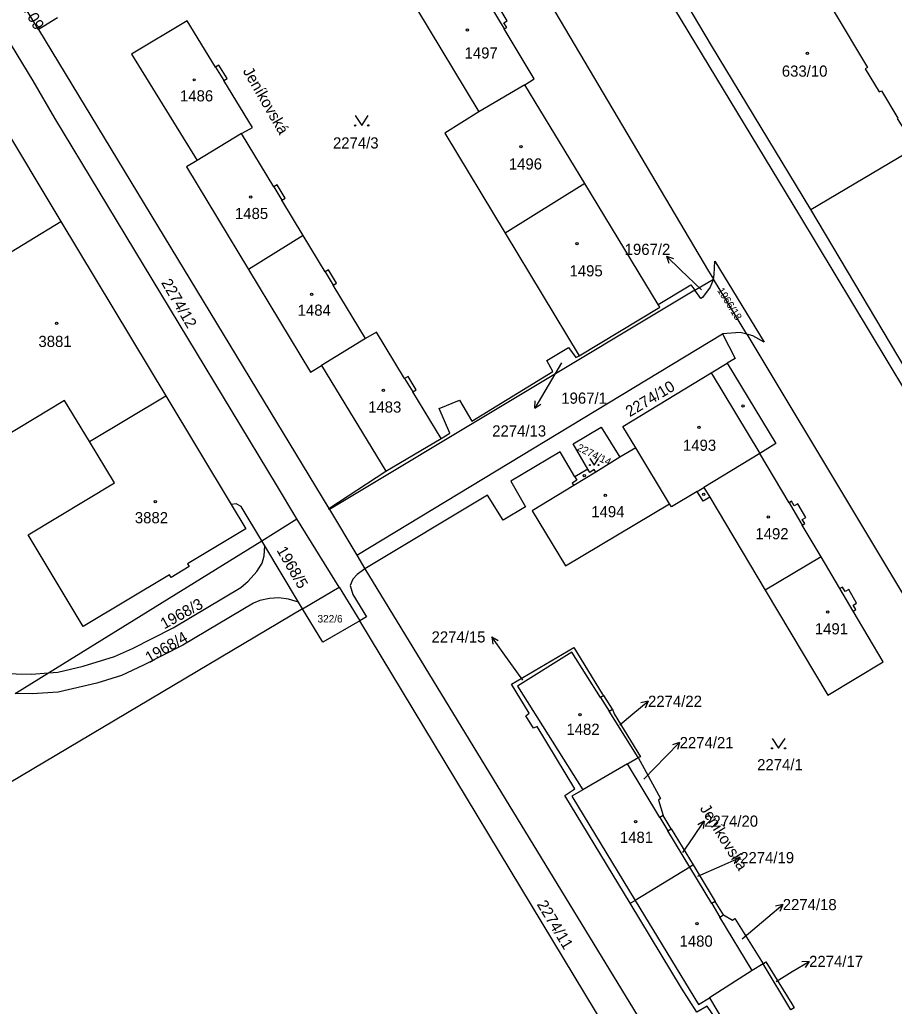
# Model space of a CAD drawing. Extents: x -679220 to -673243, y -1075091 to -1066557.
# Drawn here: x -675968.3 to -675835, y -1072476.3 to -1072325.9 of the extents above; entities that cross this region are included whole.
import ezdxf

# ---------------------------------------------------------------- set-up
doc = ezdxf.new("R2010")
doc.units = 0
for name, color, linetype in [('Hranice parcel', 7, 'Continuous'), ('Parcelní čísla', 7, 'Continuous'), ('Pop  PČ popisy', 7, 'Continuous'), ('Vnitřní kresba', 7, 'Continuous'), ('Značky budov', 7, 'Continuous'), ('Značky kultur', 7, 'Continuous')]:
    doc.layers.add(name, color=color, linetype=linetype)

msp = doc.modelspace()

# ---------------------------------------------------------------- linework, layer by layer
at = {"layer": 'Hranice parcel'}
for p, q in [((-675965.47, -1072327.41), (-675968.29, -1072322.72)), ((-675907.82, -1072324.25), (-675898.33, -1072340)), ((-675962.55, -1072325.67), (-675965.47, -1072327.41)), ((-675965.47, -1072327.41), (-675921.19, -1072400.45)), ((-675891.32, -1072335.84), (-675898.33, -1072340)), ((-675882.17, -1072350.91), (-675891.32, -1072335.84)), ((-675972.06, -1072340.04), (-675962.04, -1072356.7)), ((-675934.52, -1072343.3), (-675941.26, -1072347.38)), ((-675847.7, -1072354.86), (-675831.76, -1072345.39)), ((-675882.17, -1072350.91), (-675894.34, -1072358.45)), ((-675870.98, -1072369.33), (-675882.17, -1072350.91)), ((-675973.65, -1072363.72), (-675962.04, -1072356.7)), ((-675962.04, -1072356.7), (-675946.05, -1072383.28)), ((-675894.34, -1072358.45), (-675883.05, -1072377.15)), ((-675925.13, -1072358.83), (-675933.46, -1072363.99)), ((-675865.4, -1072367.18), (-675862.55, -1072365.47)), ((-675857.47, -1072373.89), (-675862.55, -1072365.47)), ((-675865.4, -1072367.18), (-675921.1, -1072400.6)), ((-675915.62, -1072374.53), (-675922.33, -1072378.63)), ((-675916.95, -1072407.55), (-675861.2, -1072373.83)), ((-675922.33, -1072378.63), (-675912.49, -1072394.77)), ((-675957.7, -1072390.24), (-675946.05, -1072383.28)), ((-675946.05, -1072383.28), (-675936.1, -1072399.83)), ((-675912.49, -1072394.77), (-675904.09, -1072389.77)), ((-675874.42, -1072391.2), (-675876.84, -1072392.61)), ((-675869.27, -1072399.71), (-675874.42, -1072391.2)), ((-675881.74, -1072394.44), (-675883.71, -1072395.64)), ((-675921.19, -1072400.45), (-675912.49, -1072394.77)), ((-675863.14, -1072398.71), (-675854.67, -1072412.9)), ((-675921.1, -1072400.6), (-675921.19, -1072400.45)), ((-675921.1, -1072400.6), (-675916.95, -1072407.55)), ((-675931.44, -1072405.36), (-675926.07, -1072402.03)), ((-675919.61, -1072412.41), (-675926.07, -1072402.03)), ((-675963.96, -1072425.51), (-675931.44, -1072405.36)), ((-675930.98, -1072406.12), (-675931.44, -1072405.36)), ((-675925.81, -1072414.74), (-675930.98, -1072406.12)), ((-675916.95, -1072407.55), (-675915.69, -1072409.65)), ((-675846.16, -1072407.8), (-675854.67, -1072412.9)), ((-675915.69, -1072409.65), (-675860.23, -1072500.52)), ((-675925.21, -1072415.73), (-675919.61, -1072412.41)), ((-675919.61, -1072412.41), (-675916.48, -1072417.57)), ((-675925.21, -1072415.73), (-675925.81, -1072414.74)), ((-675869.15, -1072495.9), (-675916.48, -1072417.57)), ((-675969.03, -1072428.65), (-675963.96, -1072425.51)), ((-675879.54, -1072428.71), (-675879.26, -1072428.94)), ((-675877.94, -1072431.04), (-675879.26, -1072428.94)), ((-675877.94, -1072431.04), (-675877.69, -1072431.74)), ((-675877.69, -1072431.74), (-675873.7, -1072438.31)), ((-675875.69, -1072439.35), (-675882.48, -1072443.31)), ((-675875.69, -1072439.35), (-675874.02, -1072438.38)), ((-675873.7, -1072438.31), (-675874.02, -1072438.38)), ((-675874.02, -1072438.38), (-675870.64, -1072444.67)), ((-675870.64, -1072444.67), (-675870.94, -1072444.9)), ((-675870.94, -1072444.9), (-675870.23, -1072447.25)), ((-675869, -1072449.28), (-675870.23, -1072447.25)), ((-675869, -1072449.28), (-675865.68, -1072454.75)), ((-675865.68, -1072454.75), (-675866.17, -1072455.13)), ((-675865.68, -1072454.75), (-675862.28, -1072460.33)), ((-675866.17, -1072455.13), (-675874.51, -1072460.19)), ((-675875.26, -1072460.62), (-675874.51, -1072460.19)), ((-675861.04, -1072462.39), (-675862.28, -1072460.33)), ((-675861.04, -1072462.39), (-675859.66, -1072463.21)), ((-675859.66, -1072463.21), (-675859.32, -1072462.95)), ((-675859.32, -1072462.95), (-675855.01, -1072469.85)), ((-675855.01, -1072469.85), (-675854.56, -1072469.54)), ((-675854.56, -1072469.54), (-675850.64, -1072475.95)), ((-675856.66, -1072470.89), (-675863.19, -1072475.02)), ((-675855.01, -1072469.85), (-675856.66, -1072470.89)), ((-675850.64, -1072475.95), (-675850.24, -1072476.57))]:
    msp.add_line(p, q, dxfattribs=at)
for points in [[(-675990.34, -1072122.74), (-675965.06, -1072164.5), (-675944.22, -1072198.66), (-675920.45, -1072238.88), (-675899.68, -1072273.04), (-675879.13, -1072306.74), (-675849.47, -1072355.79), (-675790.19, -1072454.14)], [(-675925.29, -1072259.54), (-675863.32, -1072364.28), (-675862.55, -1072365.47)], [(-675826.14, -1072308.69), (-675826.56, -1072309.22), (-675827.19, -1072309.93), (-675827.57, -1072310.88), (-675827.69, -1072311.75), (-675827.52, -1072312.73), (-675827.33, -1072313.58), (-675827.04, -1072314.06), (-675844.34, -1072324.49), (-675839.1, -1072333.23), (-675839.42, -1072333.42), (-675837.28, -1072336.95), (-675836.95, -1072336.77), (-675834.44, -1072340.93), (-675834.58, -1072341.01), (-675831.76, -1072345.39)], [(-675891.32, -1072335.84), (-675889.91, -1072334.94), (-675894.47, -1072327.35), (-675894.08, -1072327.12), (-675894.5, -1072326.42), (-675893.99, -1072326.11), (-675895.21, -1072324.09), (-675895.72, -1072324.4), (-675896.13, -1072323.73), (-675896.51, -1072323.96), (-675899.46, -1072319.05)], [(-675847.7, -1072354.86), (-675862.86, -1072329.89), (-675869.49, -1072318.68)], [(-675926.07, -1072402.03), (-675929.16, -1072396.81), (-675962.96, -1072340.92), (-675966.3, -1072335.23), (-675972.95, -1072324.36), (-675974.15, -1072322.36)], [(-675934.52, -1072343.3), (-675933.21, -1072342.55), (-675932.86, -1072342.34), (-675937.22, -1072335.22), (-675936.71, -1072334.91), (-675937.96, -1072332.87), (-675938.47, -1072333.19), (-675942.82, -1072326.1), (-675951.27, -1072331.19), (-675941.26, -1072347.38)], [(-675898.33, -1072340), (-675903.52, -1072343.25), (-675894.34, -1072358.45)], [(-675925.13, -1072358.83), (-675928.39, -1072353.44), (-675927.86, -1072353.12), (-675929.09, -1072351.11), (-675929.61, -1072351.42), (-675934.52, -1072343.3)], [(-675941.26, -1072347.38), (-675942.91, -1072348.38), (-675933.46, -1072363.99)], [(-675788.79, -1072452.73), (-675805.27, -1072425.65), (-675831.1, -1072382.79), (-675847.7, -1072354.86)], [(-675915.62, -1072374.53), (-675920.53, -1072366.42), (-675920.01, -1072366.1), (-675921.24, -1072364.06), (-675921.76, -1072364.38), (-675925.13, -1072358.83)], [(-675862.55, -1072365.47), (-675862.47, -1072364.77), (-675862.33, -1072362.75), (-675854.81, -1072375.09), (-675856.56, -1072374.12), (-675857.47, -1072373.89)], [(-675957.7, -1072390.24), (-675961.49, -1072383.97), (-675970.75, -1072389.56), (-675979.15, -1072375.63), (-675969.88, -1072370.05), (-675973.65, -1072363.72)], [(-675933.46, -1072363.99), (-675923.99, -1072379.64), (-675922.33, -1072378.63)], [(-675862.55, -1072365.47), (-675863.05, -1072366.69), (-675864.25, -1072368.28), (-675864.47, -1072368.43), (-675865.4, -1072367.18)], [(-675870.98, -1072369.33), (-675866.02, -1072366.34), (-675865.4, -1072367.18)], [(-675883.05, -1072377.15), (-675870.74, -1072369.74), (-675870.98, -1072369.33)], [(-675904.09, -1072389.77), (-675908.42, -1072382.64), (-675907.91, -1072382.33), (-675909.11, -1072380.31), (-675909.64, -1072380.63), (-675913.95, -1072373.54), (-675915.62, -1072374.53)], [(-675857.47, -1072373.89), (-675858.5, -1072373.62), (-675861.2, -1072373.83)], [(-675861.2, -1072373.83), (-675859.26, -1072377.56), (-675860.47, -1072378.29)], [(-675857.47, -1072373.89), (-675824.32, -1072429.06), (-675811.48, -1072450.02), (-675802.38, -1072465.38)], [(-675904.09, -1072389.77), (-675902.77, -1072388.98), (-675904.36, -1072385.2), (-675901.29, -1072383.91), (-675899.38, -1072387.14), (-675887.06, -1072379.54), (-675887.99, -1072377.86), (-675884.64, -1072375.89), (-675883.57, -1072377.45), (-675883.05, -1072377.15)], [(-675874.42, -1072391.2), (-675876.4, -1072387.92), (-675862.9, -1072379.76), (-675860.47, -1072378.29)], [(-675860.47, -1072378.29), (-675853.08, -1072390.54), (-675855.47, -1072392.05)], [(-675881.74, -1072394.44), (-675883.95, -1072390.57), (-675879.69, -1072388.02), (-675876.84, -1072392.61)], [(-675936.1, -1072399.83), (-675933.87, -1072403.53), (-675942.74, -1072408.87), (-675942.48, -1072409.3), (-675945.22, -1072410.97), (-675945.49, -1072410.53), (-675958.64, -1072418.45), (-675967.02, -1072404.45), (-675953.89, -1072396.55), (-675957.7, -1072390.24)], [(-675883.71, -1072395.64), (-675885.93, -1072391.79), (-675893.47, -1072396.3), (-675891.2, -1072400.2), (-675894.64, -1072402.2), (-675896.99, -1072398.41), (-675915.69, -1072409.65)], [(-675876.84, -1072392.61), (-675880.5, -1072394.91), (-675880.74, -1072394.52), (-675881.43, -1072394.94), (-675881.74, -1072394.44)], [(-675855.47, -1072392.05), (-675864.03, -1072397.22), (-675863.14, -1072398.71)], [(-675846.16, -1072407.8), (-675849.02, -1072402.97), (-675848.65, -1072402.75), (-675849.02, -1072402.13), (-675848.49, -1072401.82), (-675849.71, -1072399.75), (-675850.24, -1072400.05), (-675850.66, -1072399.34), (-675851.03, -1072399.56), (-675855.47, -1072392.05)], [(-675883.71, -1072395.64), (-675883.4, -1072396.14), (-675884.11, -1072396.57), (-675883.87, -1072396.96), (-675890.21, -1072400.82), (-675885.12, -1072409.18), (-675869.27, -1072399.71)], [(-675863.14, -1072398.71), (-675864.14, -1072399.31), (-675865.03, -1072397.83), (-675868.97, -1072400.21), (-675869.27, -1072399.71)], [(-675931.44, -1072405.36), (-675934.57, -1072400.14), (-675935.34, -1072399.73), (-675936.1, -1072399.83)], [(-675963.96, -1072425.51), (-675962.52, -1072425.41), (-675958.65, -1072424.49), (-675953.88, -1072423.02), (-675951.13, -1072421.8), (-675944.95, -1072418.61), (-675934.64, -1072412.48), (-675933.49, -1072411.54), (-675932.19, -1072410.03), (-675931.36, -1072408.77), (-675931.06, -1072407.66), (-675930.98, -1072406.12)], [(-675854.67, -1072412.9), (-675845.12, -1072428.88), (-675836.68, -1072423.84), (-675841.26, -1072416.08), (-675840.88, -1072415.86), (-675841.28, -1072415.18), (-675840.74, -1072414.85), (-675841.95, -1072412.8), (-675842.5, -1072413.12), (-675842.91, -1072412.42), (-675843.29, -1072412.65), (-675846.16, -1072407.8)], [(-675915.69, -1072409.65), (-675916.9, -1072410.5), (-675917.55, -1072411.23), (-675917.93, -1072412.16), (-675917.53, -1072413.56), (-675915.44, -1072416.97), (-675916.48, -1072417.57)], [(-675925.81, -1072414.74), (-675927.33, -1072414.28), (-675928.81, -1072414.06), (-675930.27, -1072414.18), (-675931.74, -1072414.48), (-675932.68, -1072414.86), (-675943.48, -1072421.27), (-675949.43, -1072424.33), (-675952.82, -1072425.88), (-675956.58, -1072427.08), (-675962.46, -1072428.45), (-675966.45, -1072428.71), (-675969.03, -1072428.65)], [(-675925.21, -1072415.73), (-675969.92, -1072442.3), (-676004.29, -1072462.79)], [(-675916.48, -1072417.57), (-675922.11, -1072420.83), (-675925.21, -1072415.73)], [(-675875.26, -1072460.62), (-675885.21, -1072444.19), (-675883.68, -1072443.19), (-675889.42, -1072433.69), (-675889.99, -1072433.95), (-675891.15, -1072432.03), (-675890.67, -1072431.62), (-675893.35, -1072427.24), (-675883.84, -1072421.61), (-675879.54, -1072428.71)], [(-675879.26, -1072428.94), (-675879.77, -1072429.26), (-675884.14, -1072422.32), (-675892.42, -1072427.54), (-675882.48, -1072443.31)], [(-675973.52, -1072425.54), (-675966.54, -1072425.69), (-675963.96, -1072425.51)], [(-675874.02, -1072438.38), (-675878.45, -1072431.36), (-675877.94, -1072431.04)], [(-675870.23, -1072447.25), (-675870.74, -1072447.55), (-675875.69, -1072439.35)], [(-675882.48, -1072443.31), (-675884.17, -1072444.3), (-675874.51, -1072460.19)], [(-675866.17, -1072455.13), (-675869.51, -1072449.59), (-675869, -1072449.28)], [(-675862.28, -1072460.33), (-675862.83, -1072460.67), (-675866.17, -1072455.13)], [(-675844.5, -1072486.02), (-675853.83, -1072491.94), (-675856.1, -1072488.21), (-675856.6, -1072488.49), (-675857.75, -1072486.5), (-675857.35, -1072486.18), (-675862.12, -1072478.41), (-675863.52, -1072476.32), (-675865.1, -1072477.2), (-675867.43, -1072473.56), (-675875.26, -1072460.62)], [(-675874.51, -1072460.19), (-675864.85, -1072476.07), (-675863.19, -1072475.02)], [(-675856.66, -1072470.89), (-675861.59, -1072462.72), (-675861.04, -1072462.39)], [(-675850.24, -1072476.57), (-675850.75, -1072476.88), (-675855.01, -1072469.85)], [(-675863.19, -1072475.02), (-675853.58, -1072491.19), (-675845.23, -1072485.98), (-675849.51, -1072478.92), (-675849, -1072478.61)]]:
    msp.add_lwpolyline(points, dxfattribs=at)
at = {"layer": 'Pop  PČ popisy'}
for p, q in [((-675867.57, -1072364.06), (-675869.73, -1072361.98)), ((-675869.73, -1072361.98), (-675868.66, -1072362.31)), ((-675869.73, -1072361.98), (-675869.36, -1072363.03)), ((-675864.38, -1072367.11), (-675867.57, -1072364.06)), ((-675885.75, -1072378.24), (-675888.29, -1072382.55)), ((-675888.29, -1072382.55), (-675889.79, -1072385.15)), ((-675889.79, -1072385.15), (-675889.72, -1072384.03)), ((-675889.79, -1072385.15), (-675888.86, -1072384.53)), ((-675894.6, -1072422.46), (-675896.36, -1072420.03)), ((-675896.36, -1072420.03), (-675895.37, -1072420.55)), ((-675896.36, -1072420.03), (-675896.18, -1072421.14)), ((-675891.62, -1072426.62), (-675894.6, -1072422.46)), ((-675874.84, -1072431.76), (-675872.54, -1072429.83)), ((-675872.54, -1072429.83), (-675873.63, -1072430.09)), ((-675872.54, -1072429.83), (-675872.99, -1072430.86)), ((-675876.83, -1072433.44), (-675874.84, -1072431.76)), ((-675869.82, -1072438.27), (-675867.73, -1072436.11)), ((-675867.73, -1072436.11), (-675868.79, -1072436.48)), ((-675867.73, -1072436.11), (-675868.07, -1072437.18)), ((-675873.16, -1072441.68), (-675869.82, -1072438.27)), ((-675865.67, -1072450.58), (-675863.99, -1072448.09)), ((-675863.99, -1072448.09), (-675864.97, -1072448.64)), ((-675863.99, -1072448.09), (-675864.14, -1072449.2)), ((-675867.21, -1072452.86), (-675865.67, -1072450.58)), ((-675861.24, -1072454.86), (-675858.5, -1072453.64)), ((-675858.5, -1072453.64), (-675859.62, -1072453.59)), ((-675858.5, -1072453.64), (-675859.21, -1072454.5)), ((-675864.94, -1072456.48), (-675861.24, -1072454.86)), ((-675854.3, -1072462.75), (-675852, -1072460.82)), ((-675852, -1072460.82), (-675853.09, -1072461.08)), ((-675852, -1072460.82), (-675852.45, -1072461.85)), ((-675858.21, -1072466.04), (-675854.3, -1072462.75)), ((-675850.55, -1072471.03), (-675847.98, -1072469.48)), ((-675847.98, -1072469.48), (-675849.09, -1072469.57)), ((-675847.98, -1072469.48), (-675848.58, -1072470.43)), ((-675853.02, -1072472.52), (-675850.55, -1072471.03))]:
    msp.add_line(p, q, dxfattribs=at)
at = {"layer": 'Vnitřní kresba'}
for p, q in [((-675896.51, -1072323.96), (-675894.47, -1072327.35)), ((-675938.47, -1072333.19), (-675937.22, -1072335.22)), ((-675929.61, -1072351.42), (-675928.39, -1072353.44)), ((-675921.76, -1072364.38), (-675920.53, -1072366.42)), ((-675909.64, -1072380.63), (-675908.42, -1072382.64)), ((-675862.9, -1072379.76), (-675855.47, -1072392.05)), ((-675880.5, -1072394.91), (-675883.87, -1072396.96)), ((-675865.03, -1072397.83), (-675864.03, -1072397.22)), ((-675851.03, -1072399.56), (-675849.02, -1072402.97)), ((-675841.26, -1072416.08), (-675843.29, -1072412.65)), ((-675879.77, -1072429.26), (-675878.45, -1072431.36)), ((-675870.74, -1072447.55), (-675869.51, -1072449.59)), ((-675862.83, -1072460.67), (-675861.59, -1072462.72))]:
    msp.add_line(p, q, dxfattribs=at)
at = {"layer": 'Značky budov'}
for centre in [(-675900.07, -1072327.52), (-675848.24, -1072331.06), (-675941.73, -1072335.1), (-675891.91, -1072345.3), (-675933.1, -1072352.97), (-675883.35, -1072360.07), (-675923.83, -1072367.8), (-675962.71, -1072372.2), (-675912.88, -1072382.43), (-675858.06, -1072384.81), (-675864.79, -1072388.09), (-675882.26, -1072395.43), (-675879.07, -1072398.45), (-675864.04, -1072398.28), (-675947.67, -1072399.41), (-675854.21, -1072401.73), (-675845.15, -1072416.22), (-675882.89, -1072431.85), (-675874.44, -1072448.16), (-675865.08, -1072463.73)]:
    msp.add_circle(centre, 0.175, dxfattribs=at)
at = {"layer": 'Značky kultur'}
for points in [[(-675917.19, -1072340.55), (-675916.19, -1072342.05), (-675915.19, -1072340.55)], [(-675881.42, -1072392.81), (-675880.75, -1072393.82), (-675880.08, -1072392.81)], [(-675853.64, -1072435.5), (-675852.64, -1072437), (-675851.64, -1072435.5)]]:
    msp.add_lwpolyline(points, dxfattribs=at)
for centre, radius in [((-675917.19, -1072342.05), 0.1), ((-675915.19, -1072342.05), 0.1), ((-675881.42, -1072393.82), 0.067), ((-675880.08, -1072393.82), 0.067), ((-675853.64, -1072437), 0.1), ((-675851.64, -1072437), 0.1)]:
    msp.add_circle(centre, radius, dxfattribs=at)

# ---------------------------------------------------------------- texts
at = {"layer": 'Parcelní čísla'}
for s, height, rotation, p in [('3709', 1.7, 300, (-675968.5, -1072323.28)), ('2274/12', 1.7, 300, (-675946.81, -1072366.01)), ('1966/18', 1.14, 302, (-675862.04, -1072367.19)), ('2274/10', 1.7, 31, (-675875.32, -1072386.54)), ('2274/14', 1.14, 334, (-675883.47, -1072391.54)), ('1968/5', 1.7, 300, (-675929.22, -1072406.8)), ('1968/3', 1.7, 29, (-675946.29, -1072418.89)), ('1968/4', 1.7, 30, (-675948.57, -1072424.05)), ('2274/11', 1.7, 301, (-675889.54, -1072460.78))]:
    msp.add_text(s, height=height, rotation=rotation, dxfattribs=at).set_placement(p)
for s, height, p in [('1497', 1.7, (-675900.51, -1072331.85)), ('633/10', 1.7, (-675852.14, -1072334.62)), ('1486', 1.7, (-675943.89, -1072338.39)), ('2274/3', 1.7, (-675920.57, -1072345.57)), ('1496', 1.7, (-675893.76, -1072348.77)), ('1485', 1.7, (-675935.51, -1072356.32)), ('1967/2', 1.7, (-675876.1, -1072361.79)), ('1495', 1.7, (-675884.51, -1072365.06)), ('1484', 1.7, (-675925.95, -1072371.06)), ('3881', 1.7, (-675965.47, -1072375.82)), ('1483', 1.7, (-675915.21, -1072385.83)), ('1967/1', 1.7, (-675885.76, -1072384.47)), ('2274/13', 1.7, (-675896.29, -1072389.47)), ('1493', 1.7, (-675867.21, -1072391.65)), ('1494', 1.7, (-675881.19, -1072401.78)), ('3882', 1.7, (-675950.77, -1072402.69)), ('1492', 1.7, (-675856.17, -1072405.14)), ('322/6', 1.14, (-675922.92, -1072417.82)), ('1491', 1.7, (-675847.11, -1072419.63)), ('2274/15', 1.7, (-675905.54, -1072420.87)), ('2274/22', 1.7, (-675872.54, -1072430.68)), ('1482', 1.7, (-675884.98, -1072434.95)), ('2274/21', 1.7, (-675867.72, -1072436.98)), ('2274/1', 1.7, (-675855.9, -1072440.34)), ('2274/20', 1.7, (-675863.98, -1072448.95)), ('1481', 1.7, (-675876.83, -1072451.41)), ('2274/19', 1.7, (-675858.49, -1072454.51)), ('2274/18', 1.7, (-675852, -1072461.67)), ('1480', 1.7, (-675867.73, -1072467.24)), ('2274/17', 1.7, (-675847.98, -1072470.33))]:
    msp.add_text(s, height=height, dxfattribs=at).set_placement(p)
at = {"layer": 'Pop  PČ popisy'}
for rotation, p in [(300, (-675934.37, -1072333.75)), (302, (-675864.7, -1072446.15))]:
    msp.add_text('Jeníkovská', height=1.7, rotation=rotation, dxfattribs=at).set_placement(p)

doc.saveas('drawing.dxf')
